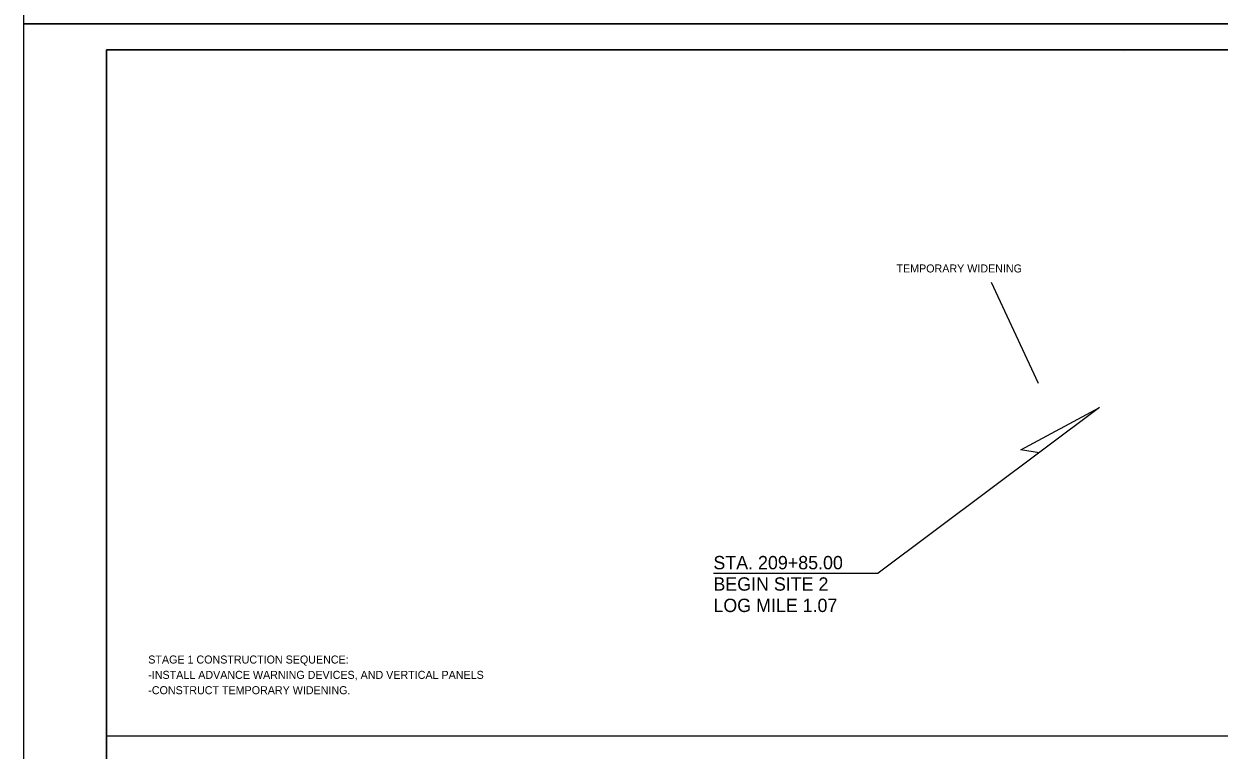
# Model space of a CAD drawing. Extents: x 1398460 to 1408037, y 380768 to 383968.
# Drawn here: x 1400666 to 1401561, y 381290 to 381834 of the extents above; entities that cross this region are included whole.
import ezdxf

# ---------------------------------------------------------------- set-up
doc = ezdxf.new("R2010")
doc.units = 0
for name, color, linetype in [('Default', 7, 'Continuous'), ('R_Border', 7, 'Continuous'), ('R_Dimension', 7, 'Continuous'), ('R_No Plot', 7, 'Continuous')]:
    doc.layers.add(name, color=color, linetype=linetype)

msp = doc.modelspace()

# ---------------------------------------------------------------- linework, layer by layer
at = {"layer": 'Default'}
for p in [(1401471.62, 381546.96), (1401182.34, 381422.86)]:
    msp.add_line(p, (1401305.83, 381422.86), dxfattribs=at)
msp.add_lwpolyline([(1401426.42, 381513.13), (1401412.64, 381515.25), (1401471.62, 381546.96)], dxfattribs=at)
at = {"layer": 'R_Border'}
for p, q in [((1400727.57, 381814.73), (1402308.47, 381814.73)), ((1400727.57, 380787.43), (1400727.57, 381814.73)), ((1401490.17, 381813.43), (1401490.17, 381813.43)), ((1401490.17, 381813.43), (1401490.17, 381813.43)), ((1400727.57, 381301.08), (1402308.47, 381301.08))]:
    msp.add_line(p, q, dxfattribs=at)
at = {"layer": 'R_Dimension'}
msp.add_line((1401390.53, 381640.86), (1401425.72, 381565.23), dxfattribs=at)
at = {"layer": 'R_No Plot'}
msp.add_line((1400665.56, 381834.2), (1402332.23, 381834.2), dxfattribs=at)
for points in [[(1400665.53, 382900.89), (1402332.23, 382900.89), (1402332.23, 381834.2), (1400665.53, 381834.2)], [(1400665.53, 381834.2), (1402332.23, 381834.2), (1402332.23, 380767.52), (1400665.53, 380767.52)], [(1400727.57, 381814.73), (1400727.57, 380787.43), (1402308.47, 380787.43), (1402308.47, 381643.67), (1402191.82, 381643.67), (1402191.82, 381765.33), (1401995.27, 381765.33), (1401995.27, 381814.73)], [(1400727.57, 381814.73), (1400727.57, 381301.08), (1402308.47, 381301.08), (1402308.47, 381643.67), (1402191.82, 381643.67), (1402191.82, 381765.33), (1401995.27, 381765.33), (1401995.27, 381814.73)], [(1401897.17, 381814.73), (1401995.27, 381814.73), (1401995.27, 381765.33), (1402075.83, 381765.33), (1402191.82, 381765.33), (1402191.82, 381643.67), (1402308.47, 381643.67), (1402308.47, 380787.43), (1400727.57, 380787.43), (1400727.57, 381814.73)], [(1400727.57, 380787.43), (1400727.57, 381301.08), (1402308.47, 381301.08), (1402308.47, 380787.43)]]:
    msp.add_lwpolyline(points, close=True, dxfattribs=at)

# ---------------------------------------------------------------- texts
at = {"layer": 'R_Border'}
msp.add_text('TEMPORARY WIDENING', height=6, dxfattribs=at).set_placement((1401319.55, 381648.08))
at = {"layer": 'R_Dimension'}
for s, height, p in [('STA. 209+85.00', 10, (1401182.34, 381425.78)), ('BEGIN SITE 2', 10, (1401182.34, 381409.78)), ('LOG MILE 1.07', 10, (1401182.34, 381393.78)), ('STAGE 1 CONSTRUCTION SEQUENCE:', 6, (1400758.75, 381355.22)), ('-INSTALL ADVANCE WARNING DEVICES, AND VERTICAL PANELS', 6, (1400758.75, 381343.74)), ('-CONSTRUCT TEMPORARY WIDENING. ', 6, (1400758.75, 381332.25))]:
    msp.add_text(s, height=height, dxfattribs=at).set_placement(p)

doc.saveas('drawing.dxf')
